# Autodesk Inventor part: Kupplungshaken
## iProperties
Created: 2004-09
Part Number: Kupplungshaken
Material: CuZn
Document SubType Name: Blech
Designer: Ulrich
Control State: 0
Master: False
Checked Out: False
Shininess: 20.0
Angle Display Precision: 2
Document Length Units: 11269
Document Angle Units: 11279
Document Time Units: 11290
Document Mass Units: 11283
Document Length Units Precision: 3
Document Angle Units Precision: 2
Density: 0.0
Volumn: 0.0
Area: 0.0
PropertySet Name: Model Information
Author: Ulrich
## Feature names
1. Biegung links
2. Biegung rechts
3. Bohrung Aufhängung [Hole]
4. Bohrung Gegengewicht [Hole]
5. Platte1
6. Platte3
7. Biegung2
8. Platte7
9. Biegung6
10. Platte8
11. Biegung7
12. Platte9
13. Biegung8
14. Platte10
15. Biegung9
16. Platte11
17. Biegung11
18. ExtrusionAbwicklung1
